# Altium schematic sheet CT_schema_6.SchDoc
size 377 x 215 mm
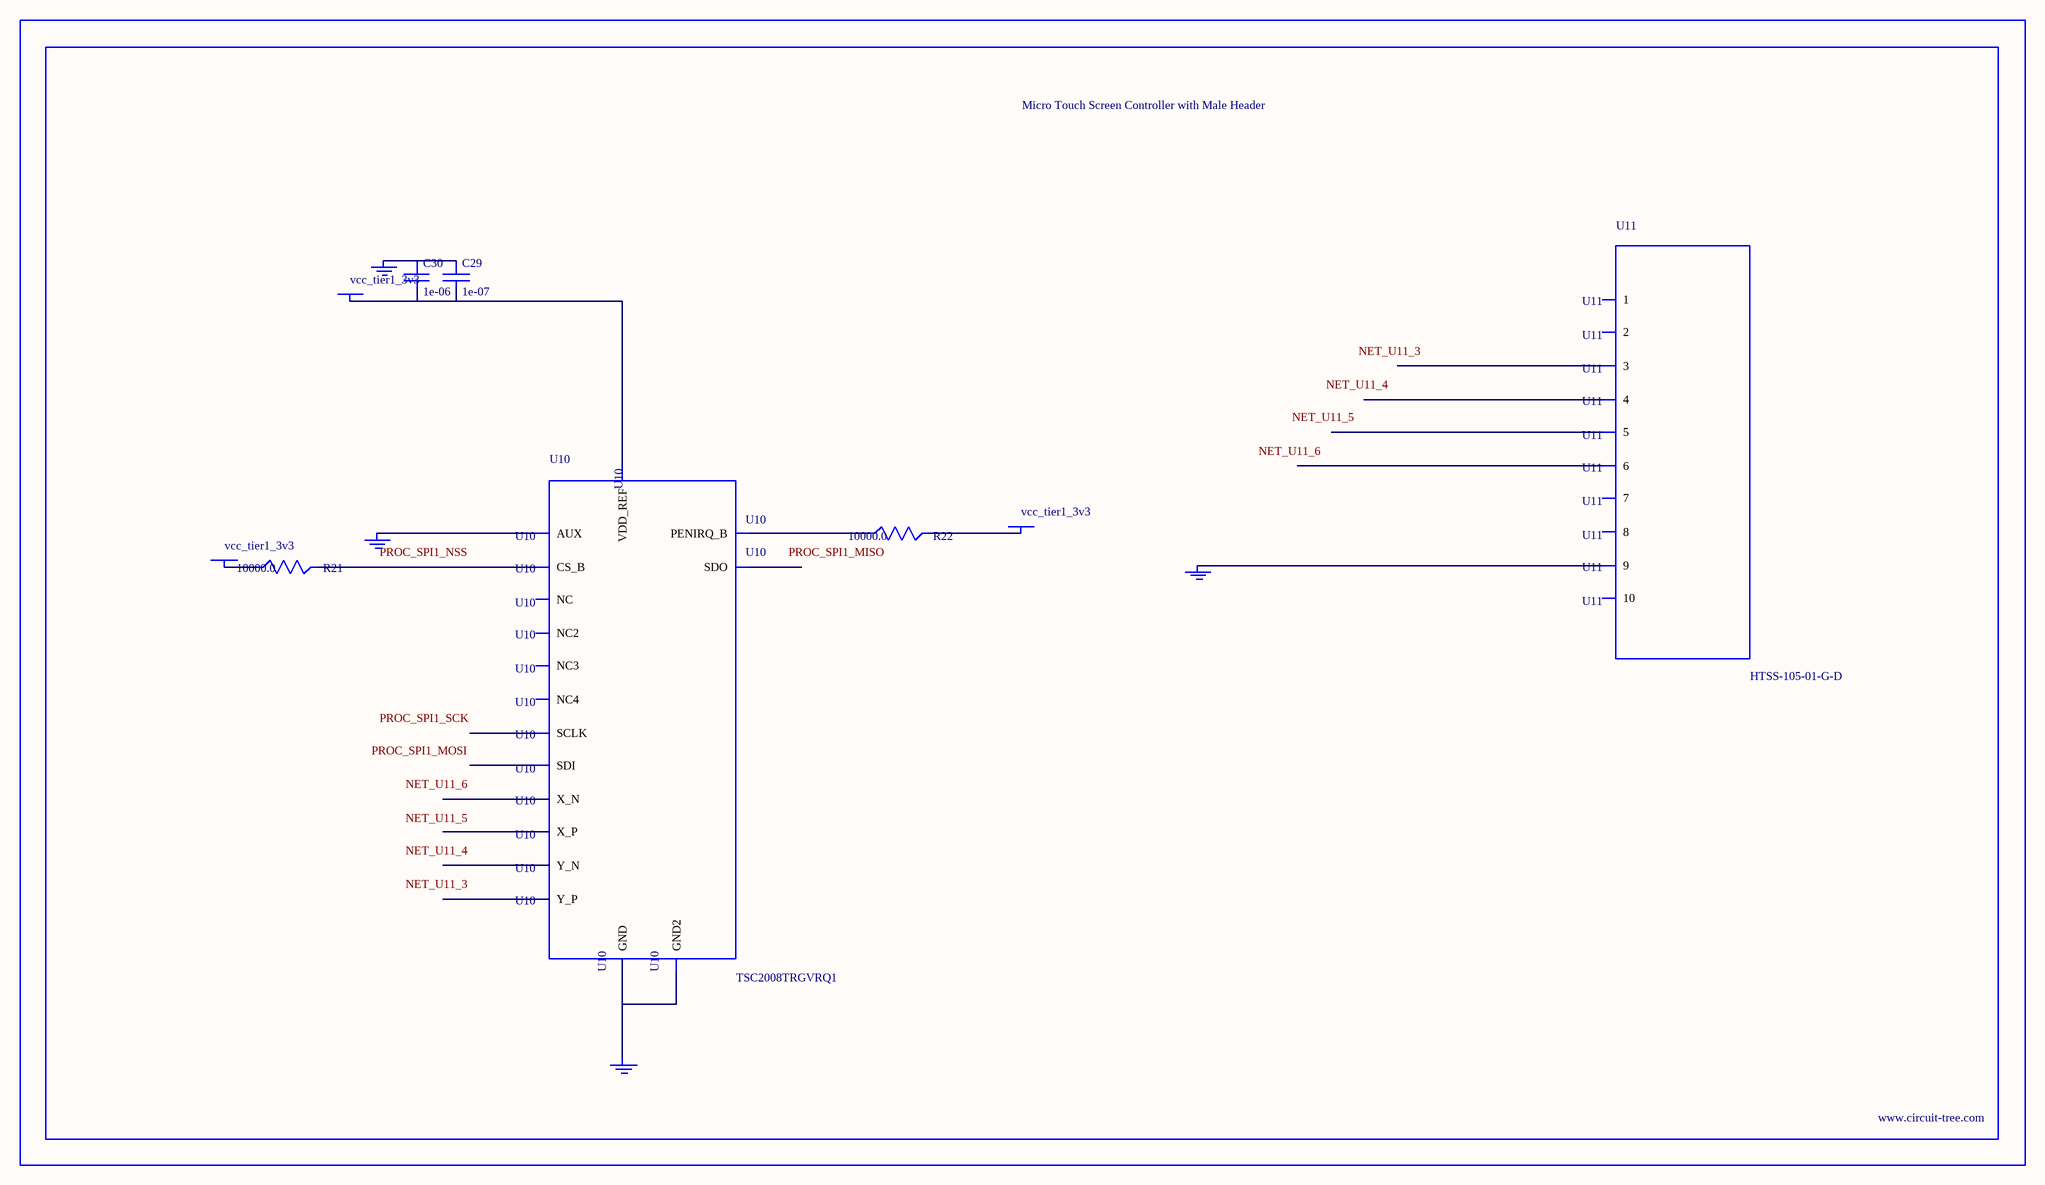
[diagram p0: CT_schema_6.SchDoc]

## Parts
BORDER5  (no value)
C29  1e-07  [C0402]
C30  1e-06  [C0603]
GND_INSTANCE_5_0  (no value)
GND_INSTANCE_5_1  (no value)
GND_INSTANCE_5_2  (no value)
GND_INSTANCE_5_3  (no value)
POWER_INSTANCE_5_0  vcc_tier1_3v3
POWER_INSTANCE_5_1  vcc_tier1_3v3
POWER_INSTANCE_5_2  vcc_tier1_3v3
R21  10000.0  [R0603]
R22  10000.0  [R0603]
U10  TSC2008TRGVRQ1  [QFN65P400X400X100-17N]
U11  HTSS-105-01-G-D  [HTSS-105-01-G-D]

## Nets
NetC29_1: C29.1 C30.1 GND_INSTANCE_5_0.0(GND)
NetC29_2: C29.2 C30.2 POWER_INSTANCE_5_1.0(PWR) U10.5(VDD_REF)
NetGND_INSTANCE_5_1_0: GND_INSTANCE_5_1.0(GND) U10.12(AUX)
NetGND_INSTANCE_5_2_0: GND_INSTANCE_5_2.0(GND) U10.10(GND) U10.17(GND2)
NetGND_INSTANCE_5_3_0: GND_INSTANCE_5_3.0(GND) U11.9
NetPOWER_INSTANCE_5_0_0: POWER_INSTANCE_5_0.0(PWR) R21.1
NetPOWER_INSTANCE_5_2_0: POWER_INSTANCE_5_2.0(PWR) R22.2
NetR21_2: R21.2 U10.3(CS_B)
NetR22_1: R22.1 U10.15(PENIRQ_B)

Not connected (* = marked no-connect by the designer): U10 1(NC) 2(SDI) 4(SCLK) 6(X_P) 7(Y_P) 8(X_N) 9(Y_N) 11(NC2) 13(NC3) 14(NC4) 16(SDO); U11 1 2 3 4 5 6 7 8 10

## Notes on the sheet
- Labels drawn without touching a wire or pin: NET_U11_3, NET_U11_4, NET_U11_5, NET_U11_6, PROC_SPI1_MISO, PROC_SPI1_MOSI, PROC_SPI1_NSS, PROC_SPI1_SCK

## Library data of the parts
BORDER5 = BORDER_PAGE5
C29 = C0402C104K3RACTU
C30 = C0603C105K3RACTU
GND_INSTANCE_5_0-GND_INSTANCE_5_3 = GND
POWER_INSTANCE_5_0-POWER_INSTANCE_5_2 = PWR
R21 R22 = RC0603JR-0710KL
